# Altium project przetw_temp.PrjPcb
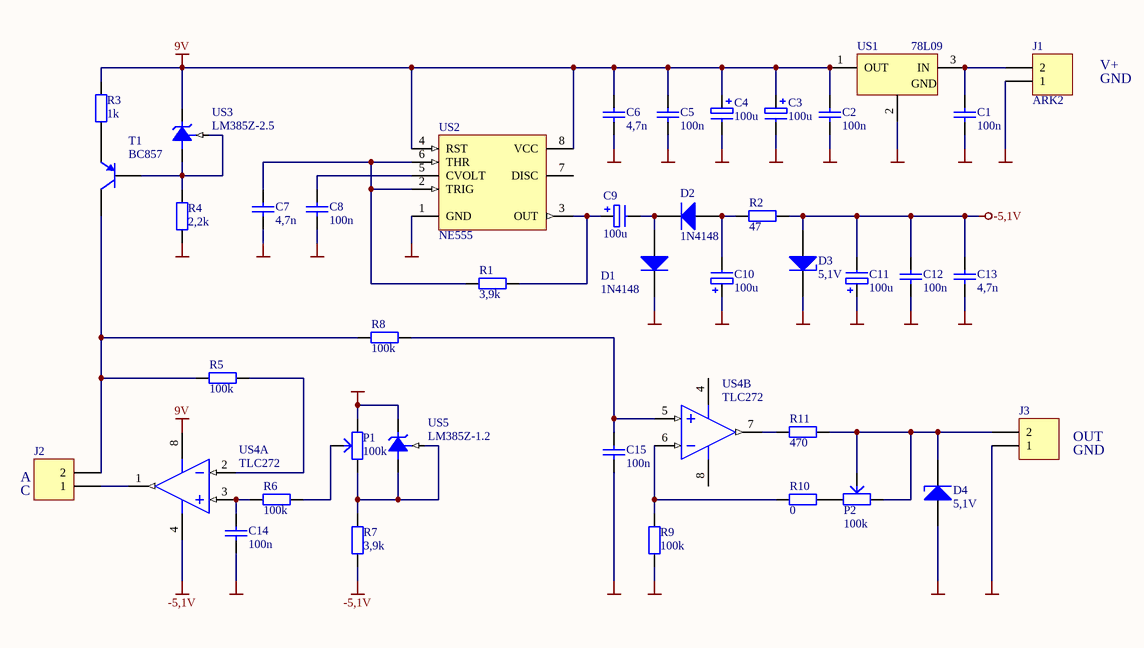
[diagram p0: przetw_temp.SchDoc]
1 sheet, 41 parts. Net scope: global (net labels, ports and power ports of the same name join across sheets).
Board file: przetw_temp.PcbDoc

## Sheet przetw_temp.SchDoc
size A4

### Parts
C1  100n  [MELF-1206]
C2  100n  [MELF-1206]
C3  100u  [2,5/5mm elektrolit]
C4  100u  [2,5/5mm elektrolit]
C5  100n  [MELF-1206]
C6  4,7n  [MELF-1206]
C7  4,7n  [MELF-1206]
C8  100n  [MELF-1206]
C9  100u  [2,5/5mm elektrolit]
C10  100u  [2,5/5mm elektrolit]
C11  100u  [2,5/5mm elektrolit]
C12  100n  [MELF-1206]
C13  4,7n  [MELF-1206]
C14  100n  [MELF-1206]
C15  100n  [MELF-1206]
D1  1N4148  [dioda MINIMELF]
D2  1N4148  [dioda MINIMELF]
D3  5,1V  [dioda MINIMELF]
D4  5,1V  [dioda MINIMELF]
J1  ARK2  [ARK2 5mm]
J2  ARK2  [ARK2 5mm]  (value not drawn)
J3  ARK2  [ARK2 5mm]  (value not drawn)
P1  100k  [pot mont poziom]
P2  100k  [pot mont poziom]
R1  3,9k  [MELF-1206]
R2  47  [MELF-1206]
R3  1k  [MELF-1206]
R4  2,2k  [MELF-1206]
R5  100k  [MELF-1206]
R6  100k  [MELF-1206]
R7  3,9k  [MELF-1206]
R8  100k  [MELF-1206]
R9  100k  [MELF-1206]
R10  0  [MELF-1206]
R11  470  [MELF-1206]
T1  BC857  [318-08]
US1  78L09  [TO92]
US2  NE555  [751-02_N]
US3  LM385Z-2.5  [Z03A]
US4  TLC272  [JG008]  (parts A,B of 2)
US5  LM385Z-1.2  [Z03A]

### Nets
9V: C2.2 C3.1 C4.1 C5.2 C6.2 R3.2 US1.1(OUT) US2.4(RST) US2.8(VCC) US3.2(+V) US4.8(VDD)
-5,1V: C11.2 C12.2 C13.2 D3.1(A) R2.2 R7.2 US4.4(GND)
GND: C1.1 C2.1 C3.2 C4.2 C5.1 C6.1 C7.1 C8.1 C10.1 C11.1 C12.1 C13.1 C14.1 C15.1 D1.2(K) D3.2(K) D4.1(A) J1.1 J3.1 P1.b R4.1 R9.1 US1.2(GND) US2.1(GND) US5.2(+V)
NetC1_2: C1.2 J1.2 US1.3(IN)
NetC7_2: C7.2 R1.1 US2.2(TRIG) US2.6(THR)
NetC8_2: C8.2 US2.5(CVOLT)
NetC9_1: C9.1 R1.2 US2.3(OUT)
NetC9_2: C9.2 D1.1(A) D2.2(K)
NetC10_2: C10.2 D2.1(A) R2.1
NetC14_2: C14.2 R6.2 US4.3(IN+)
NetC15_2: C15.2 R8.2 US4.5(IN+)
NetD4_2: D4.2(K) J3.2 P2.b P2.c R11.1
NetJ2_1: J2.1 US4.1(OUT)
NetJ2_2: J2.2 R5.2 R8.1 T1.3(C)
NetP1_a: P1.a R7.1 US5.1(-V) US5.3(FB)
NetP1_c: P1.c R6.1
NetP2_a: P2.a R10.1
NetR3_1: R3.1 T1.2(E)
NetR4_2: R4.2 T1.1(B) US3.1(-V) US3.3(FB)
NetR5_1: R5.1 US4.2(IN-)
NetR9_2: R9.2 R10.2 US4.6(IN-)
NetR11_2: R11.2 US4.7(OUT)

Not connected (* = marked no-connect by the designer): US2 7(DISC)

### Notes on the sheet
- GND
- V+
- OUT
- (near J2) A
- (near J2) C

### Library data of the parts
C1 C2 C5-C8 C12-C15 = kondensator
C3 C9-C11 = kond biegunowy: Polarized Capacitor; Value: 100u/25V
C4 = kond biegunowy: Polarized Capacitor
D1 D2 = Diode: Default Diode
D3 D4 = D Zener: Zener Diode
P1 P2 = pot mont
R1 R2 R4-R11 = rezystor
R3 = rezystor: Value: 1k 1%
T1 = BC857ALT1: General Purpose Transistor PNP Silicon
US1 = L78L08CZ: Positive Voltage Regulator
US2 = MC1455D: Timing Circuit
US3 US5 = LM285Z: Adjustable Micropower Voltage Reference; Manufacturer: National Semiconductor; CompType: Voltage Reference IC; PackageTopMarking: NSXYTT*LM285*Z
US4 = TLC272AIJG: LinCMOS Precision Dual Operational Amplifier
